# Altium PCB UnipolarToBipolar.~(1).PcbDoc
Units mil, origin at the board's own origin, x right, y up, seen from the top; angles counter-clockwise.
Board outline 3820 x 2690 mil, 2 copper layers (Top Layer, Bottom Layer), stack 62 mil thick; 43 components, 13 nets, 78 pads, 6 vias.
Unrouted connection lines stored in the file: 1.
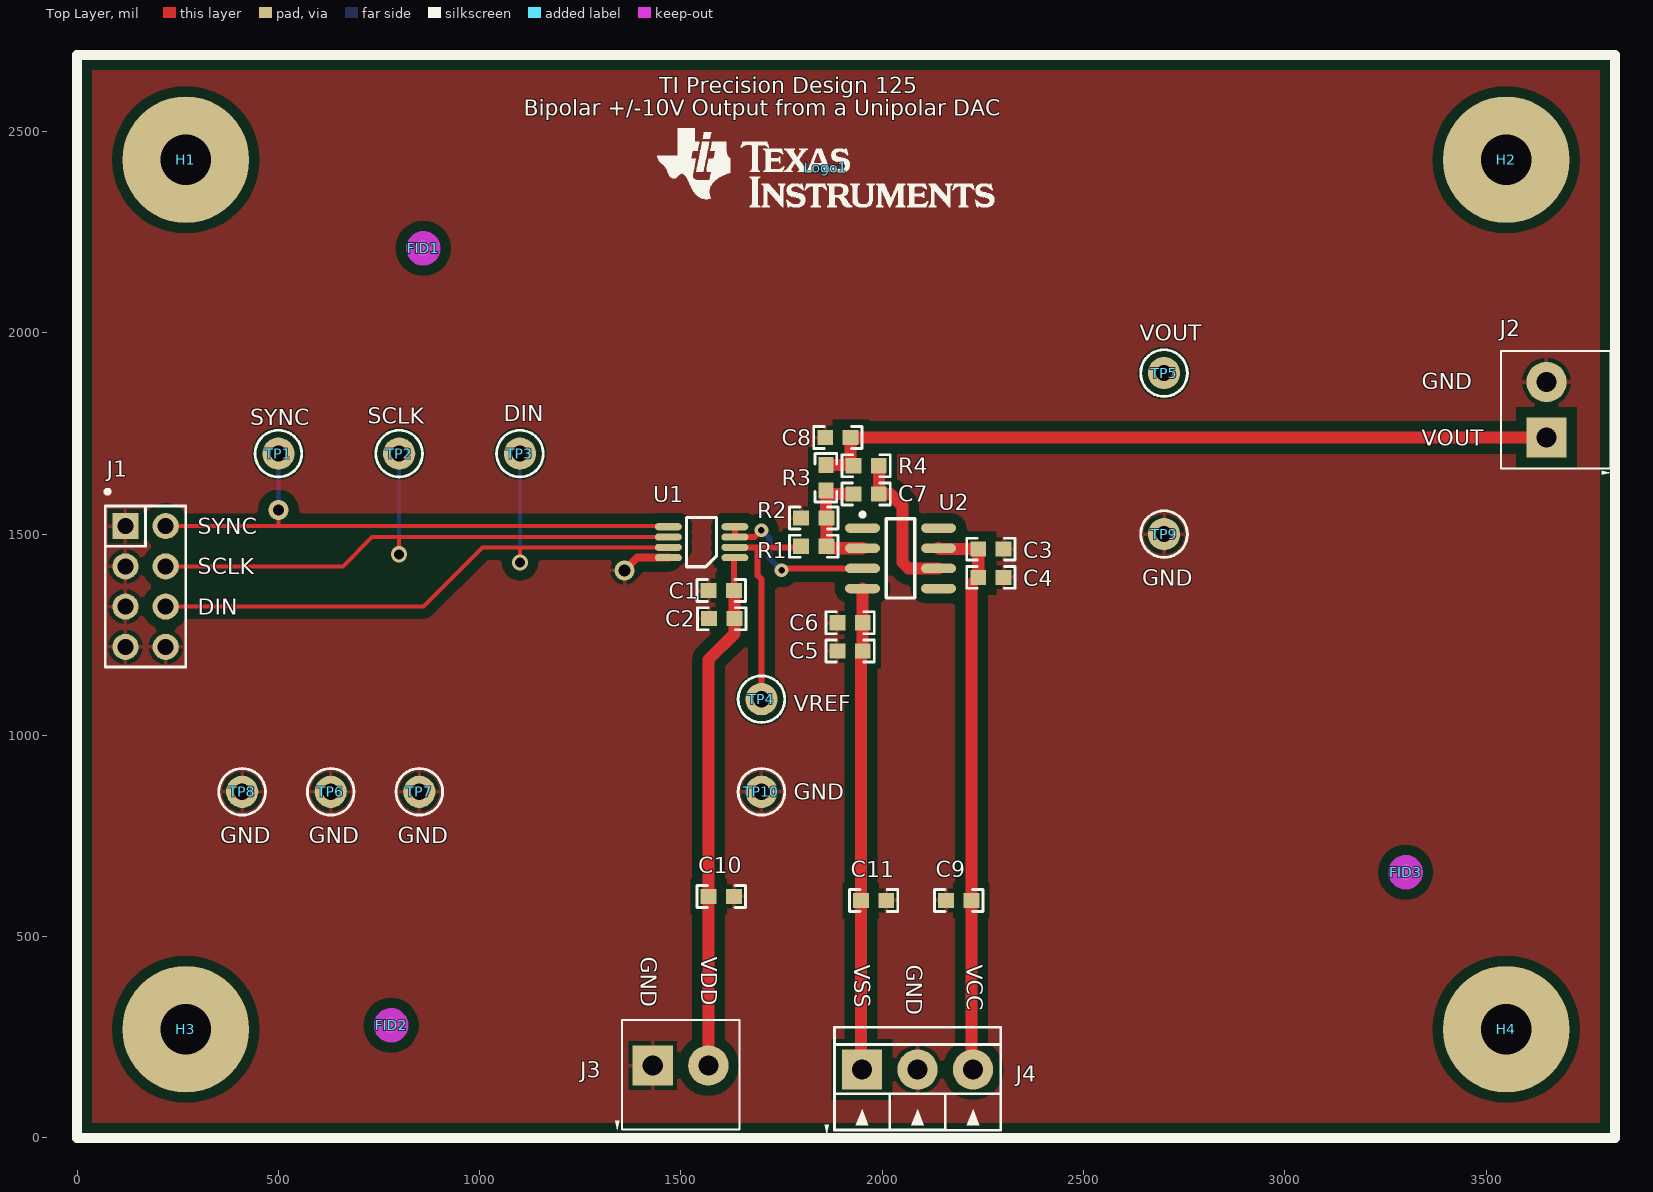
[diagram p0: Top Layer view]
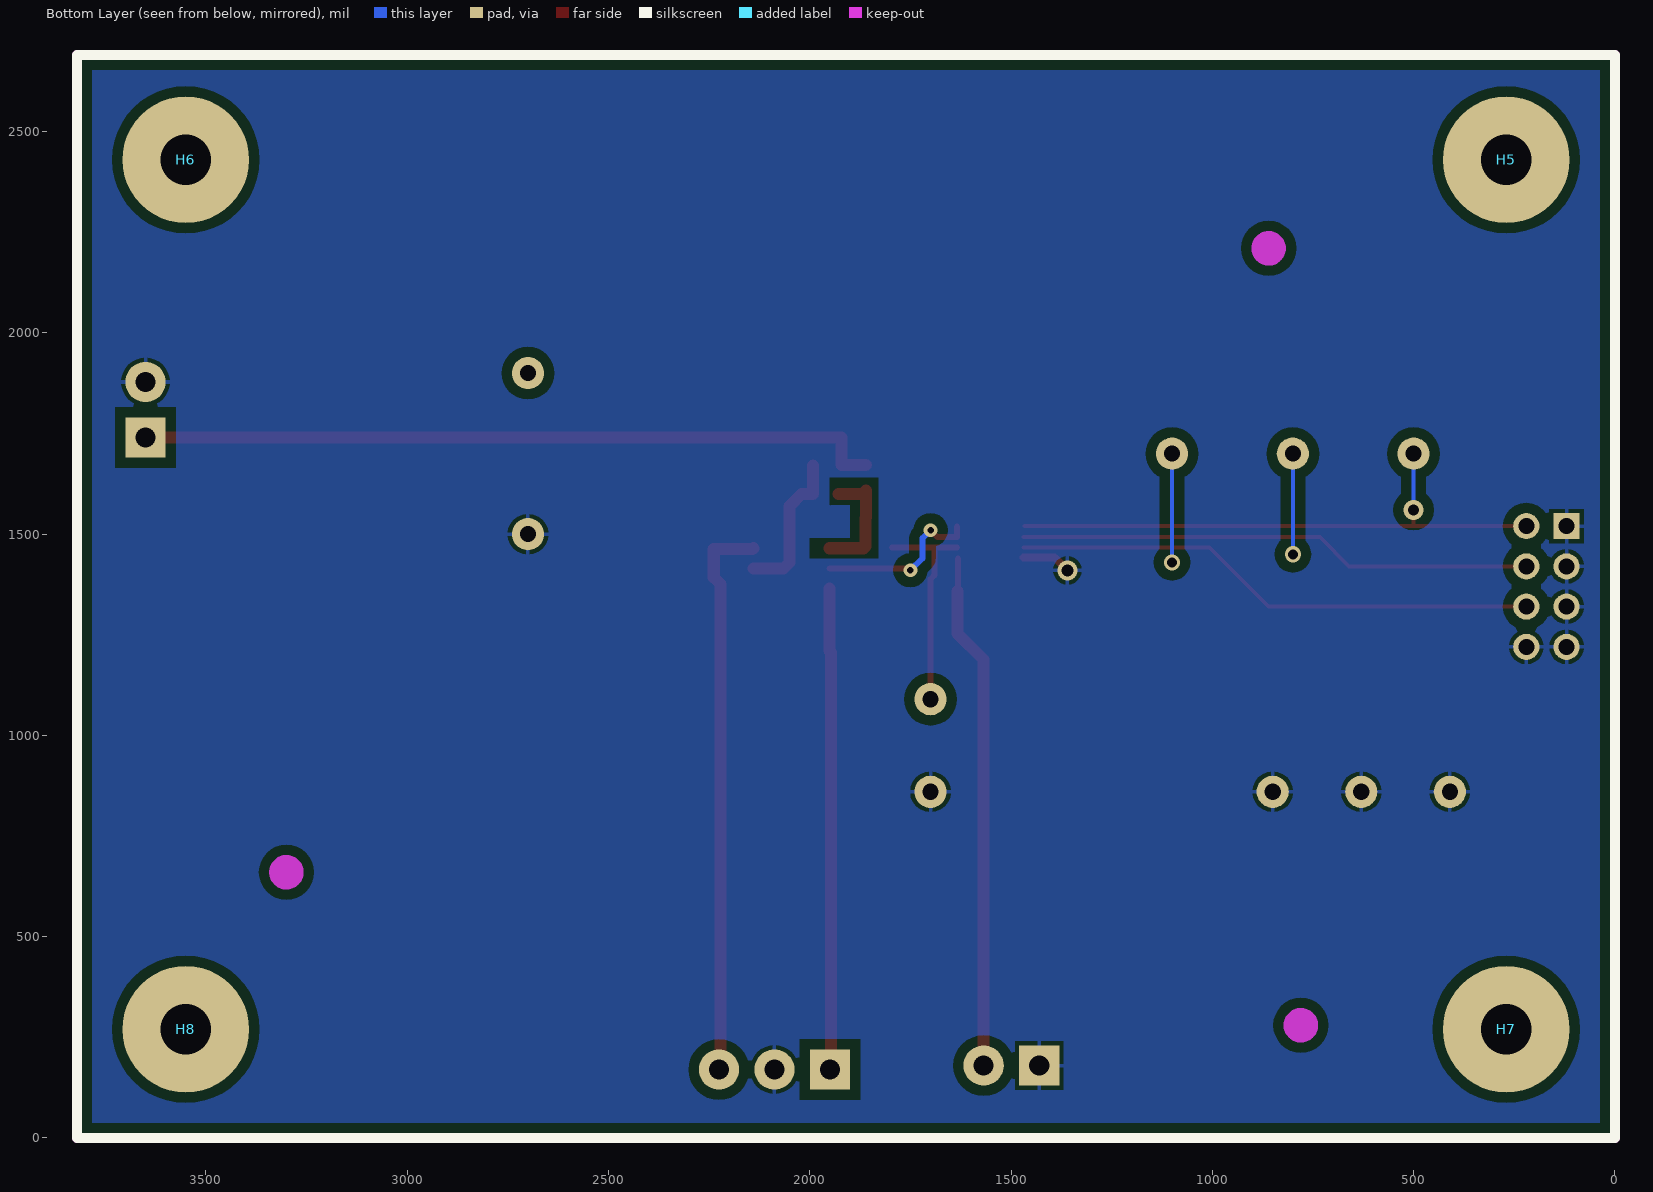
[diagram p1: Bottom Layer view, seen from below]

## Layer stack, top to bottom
Top Layer: signal copper 1.4
Dielectric: core 59.2, FR-4, Dk 4.8
Bottom Layer: signal copper 1.4

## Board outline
0,0 3820,0 3820,2690 0,2690

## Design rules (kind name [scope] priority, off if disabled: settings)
AcuteAngle [All] p1: minimum=4.50000000000000E+0001 checktracksonly=FALSE
AssemblyTestPointUsage [All] p1: valid=2
Clearance Clearance_BoardEdge_MountingHoles [OnCopper and InComponentClass('Mounting Holes') vs IsKeepOut] p1: gap=40
Clearance Clearance_BoardEdge_Poly [OnCopper and InPoly vs IsKeepOut] p2: gap=25
Clearance Clearance_BoardEdge [OnCopper and Not InComponentClass('Logo') and not InComponentClass('FiducialMark') and not InRegion(1000,500,4000,800) and Not IsKeepout vs IsKeepOut] p3: gap=75
Clearance Clearance_Poly [InPolygon] p4: gap=25
Clearance [All] p5: gap=6
ComponentClearance ComponentClearance_Logo [InComponentClass(Logo)] p1: gap=50 collisioncheckmode=3 verticalgap=10 showdistances=FALSE
ComponentClearance ComponentClearance_ScrewToNut [(HasFootprint('NY PMS 440 0025 PH')) vs (HasFootprint('Keystone_1902C'))] p2: gap=5 collisioncheckmode=3 verticalgap=10 showdistances=FALSE
ComponentClearance ComponentClearance_MountingHoles [InComponentClass('Mounting Holes')] p3: gap=250 collisioncheckmode=3 verticalgap=100000 showdistances=FALSE
ComponentClearance ComponentClearance_SmallPassives [HasFootprint('0201*') or HasFootprint('0402*') or HasFootprint('0508') or HasFootprint('0603*') or HasFootprint('0612') or HasFootprint('0805*') or HasFootprint('0815*') or HasFootprint('0830*') or HasFootprint('1206*') or HasFootprint('1210*') or HasFootprint('1808*') or HasFootprint('1812*') or HasFootprint('1825*') or HasFootprint('2010*') or HasFootprint('2220*') or HasFootprint('2225*') or HasFootprint('2512*') or HasFootprint('2728*') or HasFootprint('3518*') vs HasFootprint('0201*') or HasFootprint('0402*') or HasFootprint('0508') or HasFootprint('0603*') or HasFootprint('0612') or HasFootprint('0805*') or HasFootprint('0815*') or HasFootprint('0830*') or HasFootprint('1206*') or HasFootprint('1210*') or HasFootprint('1808*') or HasFootprint('1812*') or HasFootprint('1825*') or HasFootprint('2010*') or HasFootprint('2220*') or HasFootprint('2225*') or HasFootprint('2512*') or HasFootprint('2728*') or HasFootprint('3518*')] p4: gap=20 collisioncheckmode=3 verticalgap=10 showdistances=FALSE
ComponentClearance ComponentClearance_THtoSMT [IsThruComponent vs IsSMTComponent] p5: gap=100 collisioncheckmode=3 verticalgap=100000 showdistances=FALSE
ComponentClearance ComponentClearance_THtoTH [IsThruComponent vs IsThruComponent] p6: gap=118.11 collisioncheckmode=3 verticalgap=100000 showdistances=FALSE
ComponentClearance [All] p7: gap=40 collisioncheckmode=3 verticalgap=10 showdistances=FALSE
DiffPairsRouting [All] p1: maxlimit=100 minlimit=10 mostfreqgap=10 maxuncoupledlength=1000
FabricationTestPointUsage TestPointUsage [All] p1: valid=2 allowmultiple=FALSE
FabricationTestpoint Testpoint [All] p1: side=3 testpointundercomponent=TRUE minsize=40 maxsize=100 preferedsize=60 minholesize=0 maxholesize=40 preferedholesize=32 testpointgrid=1 allowsidetop=TRUE allowsidebottom=TRUE usegrid=TRUE gridtolerance=0.01
FanoutControl Fanout_LCC [IsLCC] p1: bgadir=Out bgaviamode=Centered fanoutstyle=Auto fanoutdirection=Alternating viagrid=1 // Fanout_LCC (Default Rule)
FanoutControl Fanout_BGA [IsBGA] p2: bgadir=Out bgaviamode=Centered fanoutstyle=Auto fanoutdirection=Alternating viagrid=1 // Fanout_BGA (Default Rule)
FanoutControl Fanout_Default [All] p4: bgadir=Out bgaviamode=Centered fanoutstyle=Auto fanoutdirection=Alternating viagrid=1 // Fanout_Default (Default Rule)
FanoutControl Fanout_Small [(CompPinCount < 5)] p5: bgadir=Out bgaviamode=Centered fanoutstyle=Auto fanoutdirection=OutThenIn viagrid=1 // Fanout_Small (Default Rule)
HoleSize [All] p1: absolutevalues=TRUE maxlimit=251 minlimit=8 maxpercent=80.000 minpercent=20.000
MinimumAnnularRing [All] p1: minimumring=9
MinimumSolderMaskSliver MinimumSolderMaskSliver_Logo [InComponentClass('Logo') vs InComponentClass('Logo')] p1: minsoldermaskwidth=0.7
MinimumSolderMaskSliver [All] p2: minsoldermaskwidth=0
PlaneConnect [All] p1: planeconnectstyle=Relief reliefexpansion=10 reliefentries=4 reliefconductorwidth=10 reliefairgap=10
PolygonConnect [All] p1: connectstyle=Relief reliefconductorwidth=10 reliefentries=4 polygonreliefangle="90 Angle" airgapwidth=10
RoutingVias [All] p1: holewidth=16 width=34 viastyle="Through Hole" minholewidth=8 minwidth=26 maxholewidth=40 maxwidth=65
SMDToCorner [All] p1: distance=30000
SilkToSilkClearance [All] p1: silktosilkclearance=5
SilkscreenOverComponentPads [All] p1: minsilkscreentomaskgap=5
SolderMaskExpansion [All] p1: expansion=3
Width [All] p1: maxlimit=100 minlimit=6 preferedwidth=10 checkconnectedcopper=TRUE
14 further rules are at their usual default settings.

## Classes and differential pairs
component class "Mounting Holes": H1 H2 H3 H4
component class Logo: Logo1
component class Hardware_ANSI-B: FID1 FID2 FID3 H1 H2 H3 H4 H5 H6 H7 H8 Logo1
component class FiducialMark: FID1 FID2 FID3
component class Header: J1
component class UnipolarToBipolar_ANSI-B: C1 C2 C3 C4 C5 C6 C7 C8 C9 C10 C11 J1 J2 J3 J4 R1 R2 R3 R4 TP1 TP2 TP3 TP4 TP5 TP6 TP7 TP8 TP9 TP10 U1 U2

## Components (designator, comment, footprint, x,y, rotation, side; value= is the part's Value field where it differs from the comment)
C1 "06033C104JAT2A" 0603 1600,1360 r180 top
C2 "06035A101JAT2A" 0603 1601.3,1290 r180 top
C3 "06033C104JAT2A" 0603 2270,1462.73 r0 top
C4 "06035A101JAT2A" 0603 2270,1392.73 r0 top
C5 "06033C104JAT2A" 0603 1920,1210 r180 top
C6 "06035A101JAT2A" 0603 1920,1280 r180 top
C7 "Used in BOM report" 0603 1960,1600 r180 top
C8 "Used in BOM report" 0603 1890,1740 r180 top
C9 "GRM1885C1H100JA01D" 0603 2190,590 r0 top
C10 "GRM1885C1H100JA01D" 0603 1600,600 r0 top
C11 "GRM1885C1H100JA01D" 0603 1978.5,590 r0 top
FID1 "Fiducial" Fiducial10-20 860,2210 r0 top
FID2 "Fiducial" Fiducial10-20 780,280 r0 top
FID3 "Fiducial" Fiducial10-20 3300,660 r0 top
H1 "NY PMS 440 0025 PH" "NY PMS 440 0025 PH" 270,2430 r0 top locked
H2 "NY PMS 440 0025 PH" "NY PMS 440 0025 PH" 3550,2430 r0 top locked
H3 "NY PMS 440 0025 PH" "NY PMS 440 0025 PH" 270,270 r0 top locked
H4 "NY PMS 440 0025 PH" "NY PMS 440 0025 PH" 3550,270 r0 top locked
H5 "1902C" Keystone_1902C 270,2430 r180 bottom locked
H6 "1902C" Keystone_1902C 3550,2430 r180 bottom locked
H7 "1902C" Keystone_1902C 270,270 r180 bottom locked
H8 "1902C" Keystone_1902C 3550,270 r180 bottom locked
J1 "TSW-104-07-G-D" TSW-104-07-G-D 170,1370 r270 top
J2 "ED555/2DS" TERM_BLK_ED555-2DS 3650,1740 r90 top
J3 "ED555/2DS" TERM_BLK_ED555-2DS 1430,180 r0 top
J4 "ED555/3DS" TERM_BLK_ED555-3DS 1950,170 r0 top
Logo1 "Texas Instruments" TI_Stacked_Overlay_Small 1860,2410 r0 top
R1 "RT0603BRD073K01L" 0603 1830,1470 r0 top
R2 "RT0603BRD074K02L" 0603 1830,1540 r0 top
R3 "RT0603BRD0712K1L" 0603 1860,1640 r90 top
R4 "Used in BOM report" 0603 1960,1670 r180 top
TP1 "SYNC" Keystone5000 500,1700 r0 top
TP2 "SCLK" Keystone5000 800,1700 r0 top
TP3 "DIN" Keystone5000 1100,1700 r0 top
TP4 "VREF" Keystone5000 1700,1090 r0 top
TP5 "VOUT" Keystone5000 2700,1900 r0 top
TP6 "GND" Keystone5001 630,860 r0 top
TP7 "GND" Keystone5001 850,860 r0 top
TP8 "GND" Keystone5001 410,860 r0 top
TP9 "GND" Keystone5001 2700,1500 r0 top
TP10 "GND" Keystone5001 1700,860 r0 top
U1 "DAC8560IDDGK" DGK0008A_N 1551.3,1480 r180 top
U2 "OPA188" 182H_N 2045.43,1440 r0 top

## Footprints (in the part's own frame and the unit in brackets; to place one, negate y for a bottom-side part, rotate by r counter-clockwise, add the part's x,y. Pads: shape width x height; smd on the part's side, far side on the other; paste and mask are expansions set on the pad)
182H_N [mm] "SOIC, 8-Leads, Body 4.9x3.9mm, Pitch 1.27mm, IPC Medium Density"
  oval 2.2x0.6 smd: 1(-2.4,1.905) 2(-2.4,0.635) 3(-2.4,-0.635) 4(-2.4,-1.905) 5(2.4,-1.905) 6(2.4,-0.635) 7(2.4,0.635) 8(2.4,1.905)
  silkscreen extent -2.52,-2.5 0.9,2.88, body extent -1.95,-2.45 1.95,2.45, height 1.75
0603 [mm] "0603 from SM-752 data"
  rect 1x0.95 smd: 1(-0.8,0) 2(0.8,0)
  silkscreen extent -1.52,-0.69 1.52,0.69, body extent -0.87,-0.47 0.87,0.47, height 0.85
DGK0008A_N [mm] "TSOP, 8-Leads, Body 3x3mm, Pitch 0.65mm, IPC Medium Density"
  oval 1.7x0.45 smd: 1(-2.1,0.975) 2(-2.1,0.325) 3(-2.1,-0.325) 4(-2.1,-0.975) 5(2.1,-0.975) 6(2.1,-0.325) 7(2.1,0.325) 8(2.1,0.975)
  silkscreen extent -0.95,-1.55 0.95,1.55, body extent -1.55,-1.55 1.55,1.55, height 1.11
Fiducial10-20 [mm]
  round 1 smd paste-0.5 mask+0.5: 1(0,0)
  Keep-Out Layer circle w1.178: c0,0 r0.5
Keystone5000 [mil] "For Keystone 500x miniature loop terminals"
  round 80 hole 40: 1(0,0)
  silkscreen extent -58,-58 58,58, body extent -49,-49 49,49, height 182
Keystone5001 [mil] "For Keystone 500x miniature loop terminals"
  round 80 hole 40: 1(0,0)
  silkscreen extent -58,-58 58,58, body extent -49,-49 49,49, height 182
Keystone_1902C [mil] "Hex Standoff, 4-40 threaded, nylon"
  body extent -145,-126 146,126, height 501
"NY PMS 440 0025 PH" [mm] "4-40 nylon screw and mounting hole"
  round 8 hole 3.2: 1(0,0)
  body extent -3.3,-3.3 3.3,3.3, height 2.69
TERM_BLK_ED555-2DS [mil]
  rect 100x100 hole 50: 1(0,0)
  round 100 hole 50: 2(138,0)
  silkscreen extent -93,-161 215,113, body extent -69,-150 207,106, height 323
TERM_BLK_ED555-3DS [mm]
  rect 2.54x2.54 hole 1.27: 1(0,0)
  round 2.54 hole 1.27: 2(3.5,0) 3(7,0)
  silkscreen extent -2.36,-4.09 8.75,2.67, body extent -1.75,-3.83 8.75,2.67, height 8.2
TI_Stacked_Overlay_Small [mil]
  silkscreen extent -418,-98 418,98
TSW-104-07-G-D [mm] "Samtec 100mil, 2x4, 230 mil above insulator"
  rect 1.65x1.65 hole 1.016 mask+0: 1(-3.81,-1.27)
  round 1.65 hole 1.016 mask+0: 2(-3.81,1.27) 3(-1.27,-1.27) 4(-1.27,1.27) 5(1.27,-1.27) 6(1.27,1.27) 7(3.81,-1.27) 8(3.81,1.27)
  silkscreen extent -6.1,-2.54 5.08,2.54, body extent -5.08,-2.54 5.08,2.54, height 8.38

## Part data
C1 C3 C5: "CAP, CERM, 0.1uF, 25V, +/-5%, X7R, 0603"
C2 C4 C6: "CAP, CERM, 100pF, 50V, +/-5%, C0G/NP0, 0603"
C7 C8: library part Capacitor, "CAP, CERM, xxxF, xxV, [TempCo], xx%, [PackageReference]"
C9 C10 C11: "CAP, CERM, 10pF, 50V, +/-5%, C0G/NP0, 0603"
FID1 FID2 FID3: "Fiducial mark.  There is nothing to buy or mount."
H1 H2 H3 H4: "Machine Screw, Round, #4-40 x 1/4, Nylon, Philips panhead"
H5 H6 H7 H8: "Standoff, Hex, 0.5\"L #4-40 Nylon"
J1: "Header, TH, 100mil, 4x2, Gold plated, 230 mil above insulator"
J2 J3: "Terminal Block, 6A, 3.5mm Pitch, 2-Pos, TH"
J4: "Terminal Block, 6A, 3.5mm Pitch, 3-Pos, TH"
Logo1: library part TI_Logo, "Texas Instrument Corporate Signature"
R1: "RES, 3.01k ohm, 0.1%, 0.1W, 0603"
R2: "RES, 4.02k ohm, 0.1%, 0.1W, 0603"
R3: "RES, 12.1k ohm, 0.1%, 0.1W, 0603"
R4: library part Resistor, "RES, xxx ohm, x%, xW, [PackageReference]"
TP1 TP2 TP3 TP4 TP5: library part 5000, "Test Point, Miniature, Red, TH"
TP6 TP7 TP8 TP9 TP10: library part 5001, "Test Point, Miniature, Black, TH"
U1: "16-Bit, Ultra-Low Glitch, Voltage Output Digital-to-Analog Converter with 2.5V, 2ppm/°C Internal Reference, DGK0008A"
U2: library part OPA650U, "Wideband, Low-Power Voltage Feedback Operational Amplifier"

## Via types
v1: diameter 40, hole 25, Top Layer to Bottom Layer, 2 vias
v2: diameter 34, hole 16, Top Layer to Bottom Layer, 2 vias
v3: diameter 50, hole 28, Top Layer to Bottom Layer, 1 vias
v4: diameter 50, hole 30, Top Layer to Bottom Layer, 1 vias

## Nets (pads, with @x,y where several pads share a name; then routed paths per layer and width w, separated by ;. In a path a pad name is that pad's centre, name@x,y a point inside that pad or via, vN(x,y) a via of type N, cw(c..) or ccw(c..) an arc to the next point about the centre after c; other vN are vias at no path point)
GND: C1.2 C2.2 C3.2 C4.2 C5.2 C6.2 C8.2 C9.1 C10.2 C11.2 J1.1 J1.3 J1.5 J1.7 J1.8 J2.2 J3.1 J4.2 R2.1 TP6.1 TP7.1 TP8.1 TP9.1 TP10.1 U1.8 | length 121.7
  Top Layer w20: v4(1360,1410) 1391.61,1441.61 U1.8
NetC7_1: C7.1 R4.1 U2.6 | length 377.1
  Top Layer w30: R4.1 C7.1 2020,1600 2050,1570 2050,1430 2065,1415 U2.6
NetC7_2: C7.2 R1.2 R2.2 R3.1 U2.2 | length 302.7
  Top Layer w30: C7.2 1868.5,1600 R3.1 1860,1541.5 R2.2 R1.2 1866.5,1465 U2.2
NetC8_1: C8.1 J2.1 R3.2 R4.2 TP5.1 | length 1853
  Top Layer w30: R3.2 R4.2@1921.5,1671.5 ; R4.2@1921.5,1677.01 C8.1 3300,1740 J2.1
NetJ1_2: J1.2 TP1.1 U1.5 | length 1427
  Top Layer w10: J1.2 500,1520 ; v3(500,1560) 500,1520 ; U1.5@1467.01,1520 500,1520
  Bottom Layer w10: v3(500,1560) TP1.1
NetJ1_4: J1.4 TP2.1 U1.6 | length 1571.6
  Top Layer w10: J1.4 660,1420 732.8,1492.8 800,1492.8 ; v1(800,1450) 800,1492.8 ; U1.6 800,1492.8
  Bottom Layer w10: v1(800,1450) TP2.1
NetJ1_6: J1.6 TP3.1 U1.7 | length 1616.8
  Top Layer w10: J1.6 860,1320 1007.2,1467.2 1100,1467.2 ; v1(1100,1430) 1100,1467.2 ; U1.7 1100,1467.2
  Bottom Layer w10: v1(1100,1430) TP3.1
NetR1_1: R1.1 TP4.1 U1.2 | length 543.1
  Top Layer w15: U1.2 1690,1467.2 ; TP4.1 1700,1388.28 1690.5,1397.78 1690.5,1466.7 1690,1467.2 ; R1.1@1795.71,1467.2 1690,1467.2
NetU1_3: U1.3 U1.4 U2.3 | length 422.5
  Top Layer w15: U1.4 U1.3 1682.8,1492.8 v2(1700,1510) ; v2(1750,1410) 1755,1415 U2.3
  Bottom Layer w15: v2(1700,1510) 1720,1490 1720,1440 v2(1750,1410)
NetU2_1: 
VCC: C3.1 C4.1 C9.2 J4.3 U2.7 | length 1395.2
  Top Layer w30: U2.7 2142.19,1462.73 C3.1 C4.1 2221.5,1375.73 C9.2 J4.3@2221.5,174.09
VDD: C1.1 C2.1 C10.1 J3.2 U1.1 | length 1283.7
  Top Layer w15: C1.1 U1.1@1631.5,1439.13
  Top Layer w30: 1568,1188 1632.8,1252.8 C2.1 C1.1@1632.8,1358.7 ; J3.2@1568.5,180.5 C10.1 1568.5,1187.5
VSS: C5.1 C6.1 C11.1 J4.1 U2.4 | length 1197.5
  Top Layer w30: J4.1 1947.01,172.99 C11.1 1947.01,1205.51 C5.1 C6.1 U2.4@1951.5,1364.45
pads on no net: FID1.1 FID2.1 FID3.1 H1.1 H2.1 H3.1 H4.1 U2.1 U2.5 U2.8

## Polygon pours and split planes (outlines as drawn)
GND on Top Layer "Top Layer-No Net" (solid, remove dead copper, pour order 4): 0,0 3820,0 3820,2690 0,2690
GND on Bottom Layer "Bottom Layer-No Net" (solid, remove dead copper, pour order 2): 0,0 3820,0 3820,2690 0,2690

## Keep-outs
Keep-Out Layer:
  lines w10: -5,0 ccw(c0,0) 0,-5 ; -5,0 ccw(c0,0) 0,-5 ; -5,0 ccw(c0,0) 0,-5 ; -5,0 ccw(c0,0) 0,-5 ; -5,0 ccw(c0,0) 0,-5 ; -5,0 ccw(c0,0) 0,-5 ; 4950,3455 cw(c4950,3450) 4955,3450 ; 4950,3455 cw(c4950,3450) 4955,3450 ; 4950,3455 cw(c4950,3450) 4955,3450 ; 4950,3455 cw(c4950,3450) 4955,3450 ; 4950,3455 cw(c4950,3450) 4955,3450 ; 4950,3455 cw(c4950,3450) 4955,3450
  lines w25: 0,0 3820,0 3820,2690 0,2690 0,0
  text ".Layer_Name" at 577,-858.49 h60

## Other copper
Top Layer:
  pour cut-out: 2000,1440 1830,1440 1830,1640 1950,1640 1950,1570 1947.27,1572.73 1900.02,1572.73 1900.02,1490.02 1900,1490 2000,1490
Bottom Layer:
  pour cut-out: 2000,1440 1830,1440 1830,1640 1950,1640 1950,1572.73 1948.63,1571.37 1947.27,1572.73 1900.02,1572.73 1900.02,1490.02 1900.04,1490 2000,1490

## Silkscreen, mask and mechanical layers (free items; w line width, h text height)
Top Overlay:
  the board outline again, w25
  text "TI Precision Design 125" at 1446.25,2595.83 h40
  text "Bipolar +/-10V Output from a Unipolar DAC" at 1110,2540 h40
  text "GND" at 3340,1860 h40
  text "VOUT" at 3340,1720 h40
  text "SYNC" at 300,1500 h40
  text "SCLK" at 300,1400 h40
  text "DIN" at 300,1300 h40
  text "GND" at 1400,450 h40 r270
  text "VDD" at 1550,450 h40 r270
  text "VSS" at 1930,430 h40 r270
  text "GND" at 2060,430 h40 r270
  text "VCC" at 2210,430 h40 r270
Bottom Overlay:
  the board outline again, w25
Top Solder:
  the board outline again, w25
Bottom Solder:
  the board outline again, w25
Drill Guide:
  text ".Layer_Name" at 577,-858.49 h60
M1 Board Outline:
  text ".Layer_Name" at 577,-858.49 h60
M2 Board Dimensions:
  rectangle: -0.5,-285.5 124.5,-160.5
  rectangle: 124.5,-410.5 499.5,-285.5
  lines w7: -0.5,-285.5 999.5,-285.5 ; 124.5,-410.5 124.5,-160.5 ; 249.5,-410.5 249.5,-160.5 ; 499.5,-410.5 499.5,-160.5 ; 749.5,-410.5 749.5,-160.5 ; -0.5,-410.5 999.5,-410.5 999.5,-160.5 -0.5,-160.5 -0.5,-410.5
  lines w10: -0.5,-475.5 -0.5,-455.5 ; 59.5,-485.5 -0.5,-465.5 ; 59.5,-445.5 -0.5,-465.5 ; 223.58,-465.5 -0.5,-465.5 ; 775.42,-465.5 999.5,-465.5 ; 939.5,-485.5 999.5,-465.5 ; 939.5,-445.5 999.5,-465.5 ; 999.5,-475.5 999.5,-455.5
  text "1000 (mil)" at 233.58,-501.49 h60
  text ".Layer_Name" at 577,-858.49 h60
M3 3D STEP Top:
  text ".Layer_Name" at 577,-858.49 h60
M4 3D STEP Bottom:
  text ".Layer_Name" at 577,-858.49 h60
M5 Assembly Top:
  lines w7: 5139,110.5 6264,110.5 ; 5139,233 6261.5,233 ; 5454,-9.5 5454,353 ; 5839,-9.5 5139,-9.5 ; 5839,353 5139,353 ; 5139,-9.5 6264,-9.5 6264,353 5139,353 ; 5139,-9.5 5139,353
  lines w10: -292,-930.17 6308,-930.17 ; -292,-726.83 6310,-726.83 ; -292,-523.5 -292,-1133.5 3713,-1133.5 6310,-1133.5 6310,-523.5 -291.5,-523.5 -291.5,-1133.5 1284,-1133.5 ; 2173,-1133.5 2173,-523.5 ; 3440,-726.83 3440,-523.5 ; 4280,-726.83 4280,-523.5 ; 4902,-1140 4902,-937.17
  text "TABLE 1" at 5526.5,388 h40
  text "Variant" at 5164,278 h40
  text "Label text" at 5599,278 h40
  text "001" at 5231.5,158 h40
  text "ChangeMe!" at 5509,155.5 h40
  text "002" at 5231.5,33 h40
  text "ChangeMe!" at 5504,30.5 h40
  text "COMPONENTS MARKED 'DNP' SHOULD NOT BE POPULATED." at 1153.5,-318.5 h60
  text "ASSEMBLY VARIANT:" at 1153,-434 h60
  text ".VariantName" at 2189,-434 h60
  text "PCB VIEWED FROM TOP SIDE" at -228.5,-655.67 h60
  text "BOARD #:" at 2248,-655.67 h60
  text ".PRJ_Number" at 2793.5,-655.67 h60
  text "REV:" at 3638,-655.67 h60
  text ".PCB_Rev" at 3929.5,-655.67 h60
  text "SVN REV:" at 4476,-655.67 h60
  text ".VersionControl_RevNumber" at 4982,-655.67 h60
  text "IGNORE ->" at -228.5,-858.49 h60
  text "PLOT NAME =" at -228.5,-1064.34 h60
  text ".plot_File_Name" at 577,-1064.34 h60
  text "GENERATED    :" at 2250,-1064.34 h60
  text ".Print_Date" at 3119.5,-1064.34 h60
  text ".Print_Time" at 3848.5,-1064.34 h60
  text "TEXAS INSTRUMENTS" at 5113,-1064.34 h60
M6 Assembly Bottom:
  lines w10: -292.5,-727.33 6309.5,-727.33 ; -290.5,-930.67 6309.5,-930.67 ; 1115.5,-1140.5 1115.5,-937.67 ; 1737.5,-727.33 1737.5,-524 ; 2577.5,-727.33 2577.5,-524 ; 3844.5,-1134 3844.5,-524 ; 4733.5,-1134 6309,-1134 6309,-524 -292.5,-524 -292.5,-1134 2304.5,-1134 6309.5,-1134 6309.5,-524
  text "COMPONENTS MARKED 'DNP' SHOULD NOT BE POPULATED." at 6102,-318 h60
  text ".VariantName" at 5058,-434 h60
  text "ASSEMBLY VARIANT:" at 6097,-434 h60
  text ".VersionControl_RevNumber" at 1035.5,-656.17 h60
  text "SVN REV:" at 1541.5,-656.17 h60
  text ".PCB_Rev" at 2088,-656.17 h60
  text "REV:" at 2379.5,-656.17 h60
  text ".PRJ_Number" at 3224,-656.17 h60
  text "BOARD #:" at 3769.5,-656.17 h60
  text "PCB VIEWED FROM BOTTOM SIDE" at 6246,-656.17 h60
  text "IGNORE ->" at 2547.85,-858.49 h60
  text "TEXAS INSTRUMENTS" at 904.5,-1064.84 h60
  text ".Print_Time" at 2169,-1064.84 h60
  text ".Print_Date" at 2898,-1064.84 h60
  text "GENERATED    :" at 3767.5,-1064.84 h60
  text ".plot_File_Name" at 5440.5,-1064.84 h60
  text "PLOT NAME =" at 6246,-1064.84 h60
M9 Title Sheet:
  drawing of 57 lines, arcs and shapes, not listed
  text "1" at 739.84,8036.5 h70
  text "2" at 3235.5,8036.5 h70
  text "3" at 5724.84,8036.5 h70
  text "4" at 8231.51,8036.5 h70
  text "5" at 10730.5,8036.5 h70
  text "6" at 13235.5,8036.5 h70
  text "A" at -416.5,6893.5 h70
  text "A" at 14383.5,6893.5 h70
  text "B" at -416.5,4513.5 h70
  text "B" at 14383.5,4513.5 h70
  text "C" at -416.5,2138.5 h70
  text "C" at 14383.5,2138.5 h70
  text "PROJECT TITLE:" at 11343.5,277.5 h45
  text ".PRJ_Title" at 11393.5,144.17 h70
  text "DESIGNED FOR:" at 11343.5,-23.5 h45
  text ".PRJ_Customer" at 11393.5,-163.5 h70
  text "D" at -416.5,-231.5 h70
  text "D" at 14383.5,-231.5 h70
  text "FILE NAME:" at 11343.5,-323.5 h45
  text ".PCB_File_Name_No_Path" at 11393.5,-443.5 h70
  text "Texas Instruments (TI) and/or its licensors do not warrant the accuracy or completeness of this specification" at 6374,-605.34 h45
  text "ENGINEER:" at 11343.5,-613.5 h45
  text "LAYOUT BY:" at 12848.5,-613.5 h45
  text "or any information contained therein. TI and/or its licensors do not warrant that this design will meet" at 6329.01,-718 h45
  text ".PRJ_Engineer" at 11393.5,-768.49 h70
  text ".PCB_Layout" at 12899,-768.49 h70
  text "the specifications, will be suitable for your application or fit for any particular purpose, or will operate in" at 6329.01,-830.67 h45
  text ".Layer_Name" at 577,-858.49 h60
  text "ALTIUM DESIGNER VERSION:" at 12848.5,-923.5 h45
  text "an implementation. TI and/or its licensors do not warrant that the design is production worthy. You should" at 6329.01,-943.33 h45
  text "completely validate and test your design implementation to confirm the system functionality for your application." at 6374,-1056 h45
  text ".print_Scale" at 11393.5,-1056.83 h70
  text ".Application_BuildNumber" at 12899,-1056.83 h70
  text "1" at 739.84,-1263.5 h70
  text "2" at 3235.5,-1263.5 h70
  text "3" at 5724.84,-1263.5 h70
  text "4" at 8231.51,-1263.5 h70
  text "5" at 10730.5,-1263.5 h70
  text "6" at 13235.5,-1263.5 h70
M10 Fab Notes:
  drawing of 207 lines, arcs and shapes, not listed
  text "DESIGN INFORMATION" at 12381.02,6810 h60
  text "(REFER ALSO ARRAY/PANEL PROFILING INFORMATION)" at 12019.46,6648.29 h60
  text "BOARD SIZE" at 11333.46,6644 h60
  text "3450MIL" at 11795.78,6516.18 h60
  text "X" at 12301.46,6516.18 h60
  text "4950MIL" at 12532.78,6516.18 h60
  text "Number of Layers :" at 11736.46,6319 h60
  text "2" at 12831.27,6309 h60
  text "MIN. TRACK WIDTH:" at 11736.46,6180 h60
  text "8" at 12832.7,6180 h60
  text "MIL" at 12987.46,6180 h60
  text "MIN. CLEARANCE:" at 11736.46,6048 h60
  text "8" at 12832.7,6048 h60
  text "MIL" at 12987.46,6048 h60
  text "MIN. VIA PAD SIZE:" at 11736.46,5916 h60
  text "24" at 12802.71,5916 h60
  text "MIL" at 12987.46,5916 h60
  text "0.05mm (2MIL)" at 12431.46,5774.29 h60
  text "MINIMUM ANNULAR RING" at 11407.23,5770 h60
  text "EXTERNAL" at 13139.46,5770 h60
  text "PER" at 11607.23,5652 h60
  text "IPC-D-275 CLASS 2 LEVEL C" at 11827.23,5652 h60
  text "MIL, HOLES" at 13315.46,5539.71 h60
  text "+/-" at 12923,5539 h60
  text "+/-" at 13777,5539 h60
  text "REGISTRATION TOLERANCES:" at 11407.23,5534 h60
  text "METAL" at 12607,5534 h60
  text "5" at 13183.2,5534 h60
  text "3" at 14016.2,5534 h60
  text "MIL" at 14132.46,5534 h60
  text "MATERIAL:" at 11332.46,5324.54 h60
  text "FR-4 High Tg" at 12318.9,5184.21 h60
  text "FR-4" at 11793.46,5175.64 h60
  text "X" at 12165.46,5175.64 h60
  text "OTHER" at 13241.46,5175.64 h60
  text "62 MIL (1.6mm) +/-10%" at 12073.56,5012.92 h60
  text "THICKNESS:" at 11407.23,5008.64 h60
  text "X" at 11945.4,5008.64 h60
  text "OTHER" at 13358.46,5008.64 h60
  text "TOLERANCE:" at 11407.23,4850.64 h60
  text "X" at 12246.53,4850.64 h60
  text "ANSI IPC-6012 TYPE 3 CLASS 2" at 12433.48,4850.64 h60
  text "OTHER +/-" at 12433.46,4694.64 h60
  text "BOW & TWIST:" at 11407.23,4537.64 h60
  text "X" at 12246.53,4537.64 h60
  text "ANSI IPC-6012 TYPE 3 CLASS 2" at 12433.48,4537.64 h60
  text "OTHER +/-" at 12433.46,4379.13 h60
  text "COPPER THICKNESS (FINISHED):" at 11332.46,4243.64 h60
  text "1.4MIL (1oz)" at 12212.46,4090.92 h60
  text "2MIL (1.4oz)" at 12979.46,4090.92 h60
  text "2.8MIL (2oz)" at 13706.46,4090.92 h60
  text "OUTER:" at 11689.46,4086.64 h60
  text "X" at 12084,4086 h60
  text "1.4MIL (1oz)" at 12212.46,3933.92 h60
  text "2.8MIL (2oz)" at 12979.46,3933.92 h60
  text "N/A" at 13706,3934.29 h60
  text "INNER SIGNAL:" at 11400.38,3929.64 h60
  text "X" at 12085.42,3929.64 h60
  text "DRILLING:" at 11332.46,3790.64 h60
  text "REFERENCE:" at 11407.23,3673.64 h60
  text "X" at 12055.46,3673.64 h60
  text "AS SHOWN" at 12242.46,3673.64 h60
  text "X" at 12956.46,3673.64 h60
  text "NC_DRILL FILES" at 13093.46,3673.64 h60
  text "PTH MIN COPPER THICKNESS:" at 11407.23,3515.64 h60
  text "X" at 12757.46,3515.64 h60
  text "1MIL" at 12894.46,3515.64 h60
  text "OTHER" at 13391.46,3515.64 h60
  text "BOARD FINISH:" at 11332.46,3356.64 h60
  text "SILKSCREEN:" at 11487.68,3238.64 h60
  text "X" at 12436.46,3238.64 h60
  text "TOP" at 12562.46,3238.64 h60
  text "X" at 12946.46,3238.64 h60
  text "BOTTOM" at 13073.46,3238.64 h60
  text "SILKSCREEN COLOR:" at 11487.68,3071.64 h60
  text "X" at 12435.42,3071.64 h60
  text "WHITE" at 12562.46,3071.64 h60
  text "OTHER" at 13073.46,3071.64 h60
  text "SOLDER RESIST COLOR:" at 11487.68,2901.64 h60
  text "X" at 12055.42,2742.44 h60
  text "GREEN" at 12182.46,2742.44 h60
  text "BLUE" at 12773.46,2742.44 h60
  text "OTHER" at 13311.46,2742.44 h60
  text "IMMERSION GOLD (ENIG)" at 12393.46,2553.92 h60
  text "SURFACE FINISH:" at 11332.46,2549.64 h60
  text "X" at 12206.51,2549.64 h60
  text "IMM. TIN/SILVER OR EQUIV" at 11662,2392.64 h60
  text "OTHER" at 13093.46,2392.64 h60
  text "ARRAY/PANEL:" at 11332.46,2213.64 h60
  text "CUT AND TRIM PER MECH LAYER 1" at 12393.46,2209.35 h60
  text "N.C. ROUTE" at 12393.46,2057.64 h60
  text "X" at 13072.46,2057.64 h60
  text "V. SCORE" at 13259.46,2057.64 h60
  text "CERTIFICATION:" at 11332.46,1920.64 h60
  text "MATERIALS AND WORKMANSHIP FOR ALL PCBS" at 12057.46,1920.64 h60
  text "TO MEET OR EXCEED THE REQUIREMENTS OF:" at 12057.46,1822.64 h60
  text "X" at 11683.96,1686.13 h60
  text "ANSI IPC-A-600F CLASS ->" at 11822.96,1686.13 h60
  text "X" at 13462.02,1686.13 h60
  text "2" at 13580.96,1686.14 h60
  text "1" at 13265.96,1684.64 h60
  text "3" at 13934.96,1684.64 h60
  text "X" at 11686.02,1526.64 h60
  text "UL 94V-0" at 11822.96,1526.64 h60
  text "X" at 12498.02,1526.64 h60
  text "RoHS" at 12634.96,1526.64 h60
  text "OTHER" at 13279.36,1526.64 h60
  text "PER ORDER" at 13676.42,1526.64 h60
  text "ADDITIONAL REQUIREMENTS:" at 11332.46,1385.64 h60
  text "MICROSECTION:" at 11407.23,1270.64 h60
  text "YES" at 12312.96,1270.64 h60
  text "REQUIRED" at 13174.46,1114.49 h60
  text "BARE BOARD ELEC. TEST:" at 11407.23,1111.64 h60
  text "NONE" at 12712.96,1111.64 h60
  text "X" at 13047.46,1111.64 h60
  text "PER ORDER" at 13766.46,1111.64 h60
  text "MANUFACTURER'S ID/LOGO:" at 11407.23,954.64 h60
  text "RAIL" at 12872.96,950.35 h60
  text "X" at 13247.46,950.35 h60
  text "METAL" at 13364.77,950.35 h60
  text "SILK" at 13876.46,950.35 h60
  text ".Layer_Name" at 577,-858.49 h60
M11 Gerber Information:
  lines w10: -292,-930.17 6308,-930.17 ; -292,-726.83 6310,-726.83 ; -292,-523.5 -292,-1133.5 3713,-1133.5 6310,-1133.5 6310,-523.5 -291.5,-523.5 -291.5,-1133.5 1284,-1133.5 ; 2173,-1133.5 2173,-523.5 ; 3440,-726.83 3440,-523.5 ; 4280,-726.83 4280,-523.5 ; 4902,-1140 4902,-937.17
  text "ALL ARTWORK VIEWED FROM TOP SIDE" at -228.5,-655.67 h60
  text "BOARD #:" at 2248,-655.67 h60
  text ".PRJ_Number" at 2793.5,-655.67 h60
  text "REV:" at 3638,-655.67 h60
  text ".PCB_Rev" at 3929.5,-655.67 h60
  text "SVN REV:" at 4476,-655.67 h60
  text ".VersionControl_RevNumber" at 4982,-655.67 h60
  text "LAYER NAME =" at -228.5,-858.49 h60
  text "PLOT NAME =" at -228.5,-1064.34 h60
  text ".plot_File_Name" at 577,-1064.34 h60
  text "GENERATED    :" at 2250,-1064.34 h60
  text ".Print_Date" at 3119.5,-1064.34 h60
  text ".Print_Time" at 3848.5,-1064.34 h60
  text "TEXAS INSTRUMENTS" at 5113,-1064.34 h60
M12 Stackup:
  lines w6: 11360,7460 13910,7460 ; 11360,7564.4 13910,7564.4 ; 11300,6975 ccw(c11334,6975) 11334,6941 13936,6941 ccw(c13936,6975) 13970,6975 13970,7681 ccw(c13936,7681) 13936,7715 11334,7715 ccw(c11334,7681) 11300,7681 11300,6975
  text "The Stackup Legend below this is static." at 11605.5,7874.5 h60
  text "If you change the stackup, update the Legend." at 11615.5,7784.5 h60
  text "Layer Stack Up Detail for: Ref_Design.PcbDoc" at 11360,7597.1 h57
  text "Layer" at 11360,7525.4 h24
  text "Gerber" at 12255.81,7525.4 h24
  text "Copper" at 12819.33,7525.4 h24
  text "Dielectric" at 13422.04,7525.4 h24
  text "Name" at 11360,7477.4 h24
  text "Document" at 12255.81,7477.4 h24
  text "Thickness" at 12819.33,7477.4 h24
  text "Material" at 13422.04,7477.4 h24
  text "Top Solder Mask" at 11360,7384.44 h34
  text "(.GTS)" at 12255.81,7384.44 h34
  text "Solder Resist" at 13422.04,7384.44 h34
  text "Top Layer" at 11360,7287.69 h34
  text "(.GTL)" at 12255.81,7287.69 h34
  text "1.4mil" at 12819.33,7287.69 h34
  text "FR-4" at 13422.04,7239.31 h34
  text "Bottom Layer" at 11360,7190.94 h34
  text "(.GBL)" at 12255.81,7190.94 h34
  text "1.4mil" at 12819.33,7190.94 h34
  text "Bottom Solder Mask" at 11360,7094.19 h34
  text "(.GBS)" at 12255.81,7094.19 h34
  text "Solder Resist" at 13422.04,7094.19 h34
  text ".Layer_Name" at 577,-858.49 h60
M13 Component Bodies Top:
  text ".Layer_Name" at 577,-858.49 h60
M14 Component Bodies Bottom:
  text ".Layer_Name" at 577,-858.49 h60
M15 Courtyards Top:
  text ".Layer_Name" at 577,-858.49 h60
M16 Courtyards Bottom:
  text ".Layer_Name" at 577,-858.49 h60

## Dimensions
0,0 to 0,2690 on M2 Board Dimensions
0,0 to 3820,0 on M2 Board Dimensions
